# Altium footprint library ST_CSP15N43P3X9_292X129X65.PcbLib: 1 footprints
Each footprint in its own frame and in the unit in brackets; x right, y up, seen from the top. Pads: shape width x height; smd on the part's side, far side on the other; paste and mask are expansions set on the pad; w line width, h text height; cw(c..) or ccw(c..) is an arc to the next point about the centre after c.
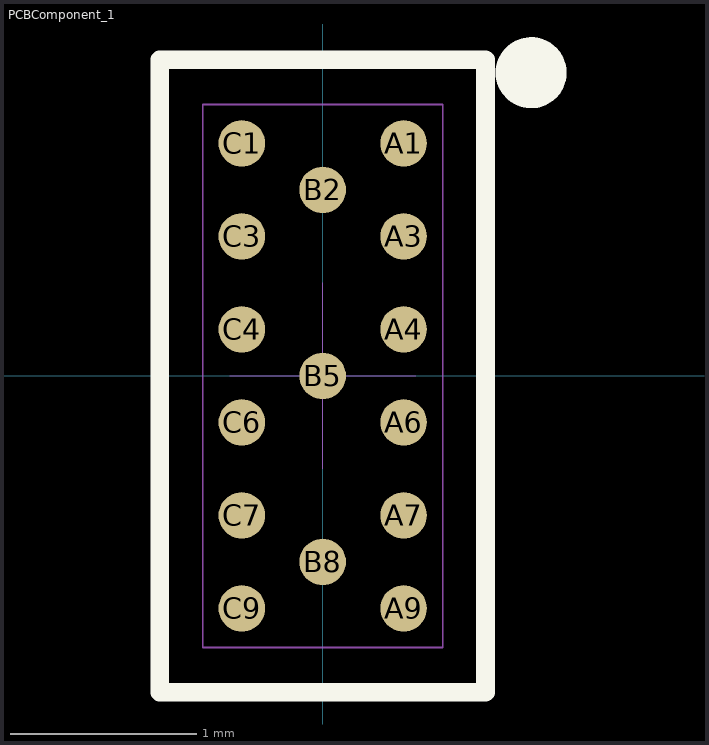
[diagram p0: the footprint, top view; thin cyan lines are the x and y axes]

## PCBComponent_1 [mm]
pads (15):
  round 0.25 smd paste-20 mask+0.05: A1(0.435,1.25) A3(0.435,0.75) A4(0.435,0.25) A6(0.435,-0.25) A7(0.435,-0.75) A9(0.435,-1.25) B2(0,1) B5(0,0) B8(0,-1) C1(-0.435,1.25) C3(-0.435,0.75) C4(-0.435,0.25) C6(-0.435,-0.25) C7(-0.435,-0.75) C9(-0.435,-1.25)
Top Overlay:
  circle w0.2: c1.121,1.63 r0.091
  lines w0.1: -0.875,-1.7 -0.875,1.7 0.875,1.7 0.875,-1.7 -0.875,-1.7
Top Paste:
  rectangle: -0.6,-1.415 -0.27,-1.085
  rectangle: 0.27,-1.415 0.6,-1.085
  rectangle: 0.27,-0.915 0.6,-0.585
  rectangle: -0.165,-1.165 0.165,-0.835
  rectangle: -0.6,-0.915 -0.27,-0.585
  rectangle: -0.6,-0.415 -0.27,-0.085
  rectangle: 0.27,-0.415 0.6,-0.085
  rectangle: 0.27,0.085 0.6,0.415
  rectangle: -0.165,-0.165 0.165,0.165
  rectangle: -0.6,0.085 -0.27,0.415
  rectangle: 0.27,0.585 0.6,0.915
  rectangle: -0.6,0.585 -0.27,0.915
  rectangle: -0.165,0.835 0.165,1.165
  rectangle: 0.27,1.085 0.6,1.415
  rectangle: -0.6,1.085 -0.27,1.415
Mechanical 15:
  lines w0.001: -0.5,0 0.5,0 ; 0,-0.5 0,0.5
  lines w0.01: -0.645,-1.46 -0.645,1.46 0.645,1.46 0.645,-1.46 -0.645,-1.46
3D body: height 0.65, standoff 0.32, extent -0.645,-1.46 0.645,1.46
